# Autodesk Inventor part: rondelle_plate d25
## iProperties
Author: chr
Created: 2002-03
Part Number: rondelle_plate d25
Material: Par défaut
Document SubType Name: Modélisation
Designer: chr
Control State: 0
Master: False
Checked Out: False
PropertySet Name: Design Tracking Control
Shininess: 20.0
Angle Display Precision: 2
Document Length Units: 11269
Document Angle Units: 11283
Document Time Units: 11279
Document Mass Units: 11290
Document Length Units Precision: 3
Document Angle Units Precision: 2
Compacted: False
PropertySet Name: _Private Model Information
Density: 0.0
Volumn: 0.0
Area: 0.0
PropertySet Name: Model Information
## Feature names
1. Base1
